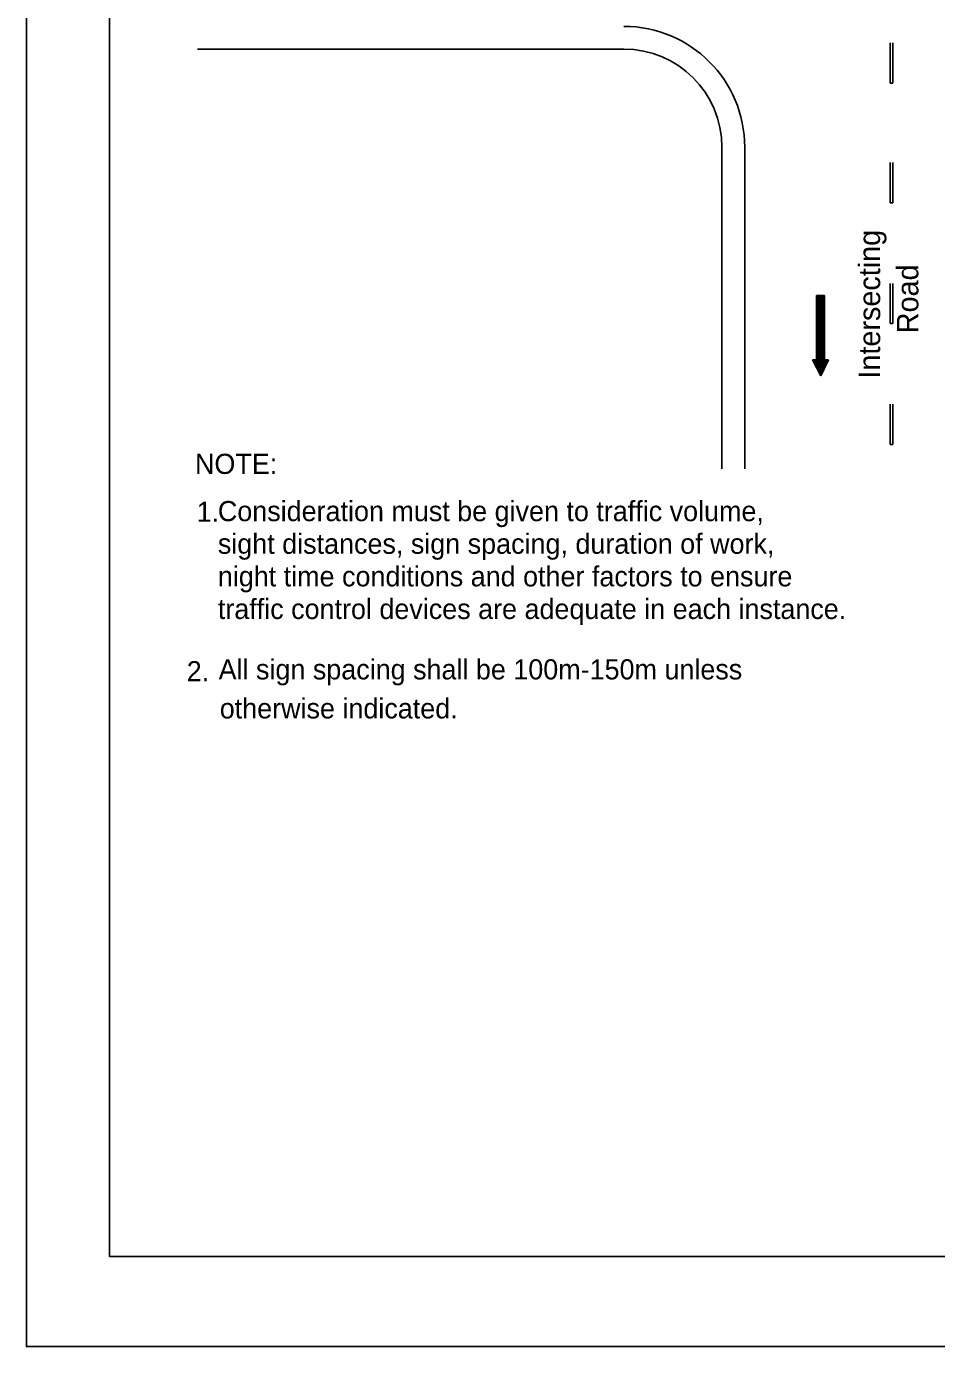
# Model space of a CAD drawing. Extents: x 1833 to 2049, y 205 to 484.
# Drawn here: x 1833.5 to 1942.9, y 205.4 to 364.1 of the extents above; entities that cross this region are included whole.
import ezdxf

# ---------------------------------------------------------------- set-up
doc = ezdxf.new("R2010")
doc.units = 0
for name, color, linetype in [('Level 10', 7, 'Continuous'), ('Level 2', 7, 'Continuous'), ('Level 60', 7, 'Continuous')]:
    doc.layers.add(name, color=color, linetype=linetype)

msp = doc.modelspace()

# ---------------------------------------------------------------- linework, layer by layer
at = {"layer": 'Level 10'}
for p, q in [((1854.04, 361.34), (1905.27, 361.34)), ((1917.06, 349.55), (1917.06, 310.88)), ((1919.79, 349.55), (1919.79, 310.88)), ((1928.43, 323.99), (1928.43, 331.74)), ((1929.4, 331.74), (1928.43, 331.74)), ((1928.43, 323.03), (1928.43, 331.74)), ((1928.55, 322.79), (1928.55, 331.74)), ((1928.68, 322.54), (1928.68, 331.74)), ((1928.8, 322.3), (1928.8, 331.74)), ((1928.92, 322.06), (1928.92, 331.74)), ((1929.04, 322.3), (1929.04, 331.74)), ((1929.16, 322.54), (1929.16, 331.74)), ((1929.28, 322.79), (1929.28, 331.74)), ((1929.4, 323.99), (1929.4, 331.74)), ((1929.4, 323.03), (1929.4, 331.74)), ((1928.92, 322.06), (1927.95, 323.99)), ((1928.43, 323.99), (1927.95, 323.99)), ((1928.07, 323.75), (1928.07, 323.99)), ((1928.19, 323.51), (1928.19, 323.99)), ((1928.31, 323.27), (1928.31, 323.99)), ((1928.92, 322.06), (1929.88, 323.99)), ((1929.88, 323.99), (1929.4, 323.99)), ((1929.52, 323.27), (1929.52, 323.99)), ((1929.64, 323.51), (1929.64, 323.99)), ((1929.76, 323.75), (1929.76, 323.99)), ((1850.33, 216.2), (1850.33, 216.2))]:
    msp.add_line(p, q, dxfattribs=at)
for radius in [14.52, 11.79]:
    msp.add_arc((1905.27, 349.55), radius, 0, 90, dxfattribs=at)
at = {"layer": 'Level 2'}
for p, q in [((1937.29, 362.09), (1937.29, 357.25)), ((1937.58, 357.25), (1937.58, 362.09)), ((1937.29, 357.25), (1937.58, 357.25)), ((1937.29, 347.69), (1937.29, 342.85)), ((1937.58, 342.85), (1937.58, 347.69)), ((1937.29, 342.85), (1937.58, 342.85)), ((1937.29, 333.18), (1937.29, 328.34)), ((1937.58, 328.34), (1937.58, 333.18)), ((1937.29, 328.34), (1937.58, 328.34)), ((1937.29, 318.66), (1937.29, 313.83)), ((1937.58, 313.83), (1937.58, 318.66)), ((1937.29, 313.83), (1937.58, 313.83))]:
    msp.add_line(p, q, dxfattribs=at)
at = {"layer": 'Level 60'}
for p, q in [((1843.46, 216.2), (1843.46, 216.2)), ((1833.46, 205.39), (1833.46, 205.39))]:
    msp.add_line(p, q, dxfattribs=at)
for points in [[(2049.46, 484.39), (1833.46, 484.39), (1833.46, 205.39), (2049.46, 205.39)], [(2030.33, 473.58), (1843.46, 473.58), (1843.46, 216.2), (2030.33, 216.2)]]:
    msp.add_lwpolyline(points, close=True, dxfattribs=at)

# ---------------------------------------------------------------- texts
at = {"layer": 'Level 10'}
for s, p in [('Intersecting', (1936.07, 321.74)), ('Road', (1940.66, 327.19))]:
    msp.add_text(s, height=2.585, rotation=90, dxfattribs=at).set_placement(p)
for s, p in [('NOTE:', (1853.72, 310.28)), ('1.', (1853.93, 304.53)), ('Consideration must be given to traffic volume,', (1856.47, 304.6)), ('sight distances, sign spacing, duration of work,', (1856.47, 300.68)), ('night time conditions and other factors to ensure', (1856.47, 296.76)), ('traffic control devices are adequate in each instance.', (1856.47, 292.84)), ('2.', (1852.73, 285.36)), ('All sign spacing shall be 100m-150m unless', (1856.56, 285.58)), ('otherwise indicated.', (1856.7, 280.89))]:
    msp.add_text(s, height=2.419, dxfattribs=at).set_placement(p)

doc.saveas('drawing.dxf')
